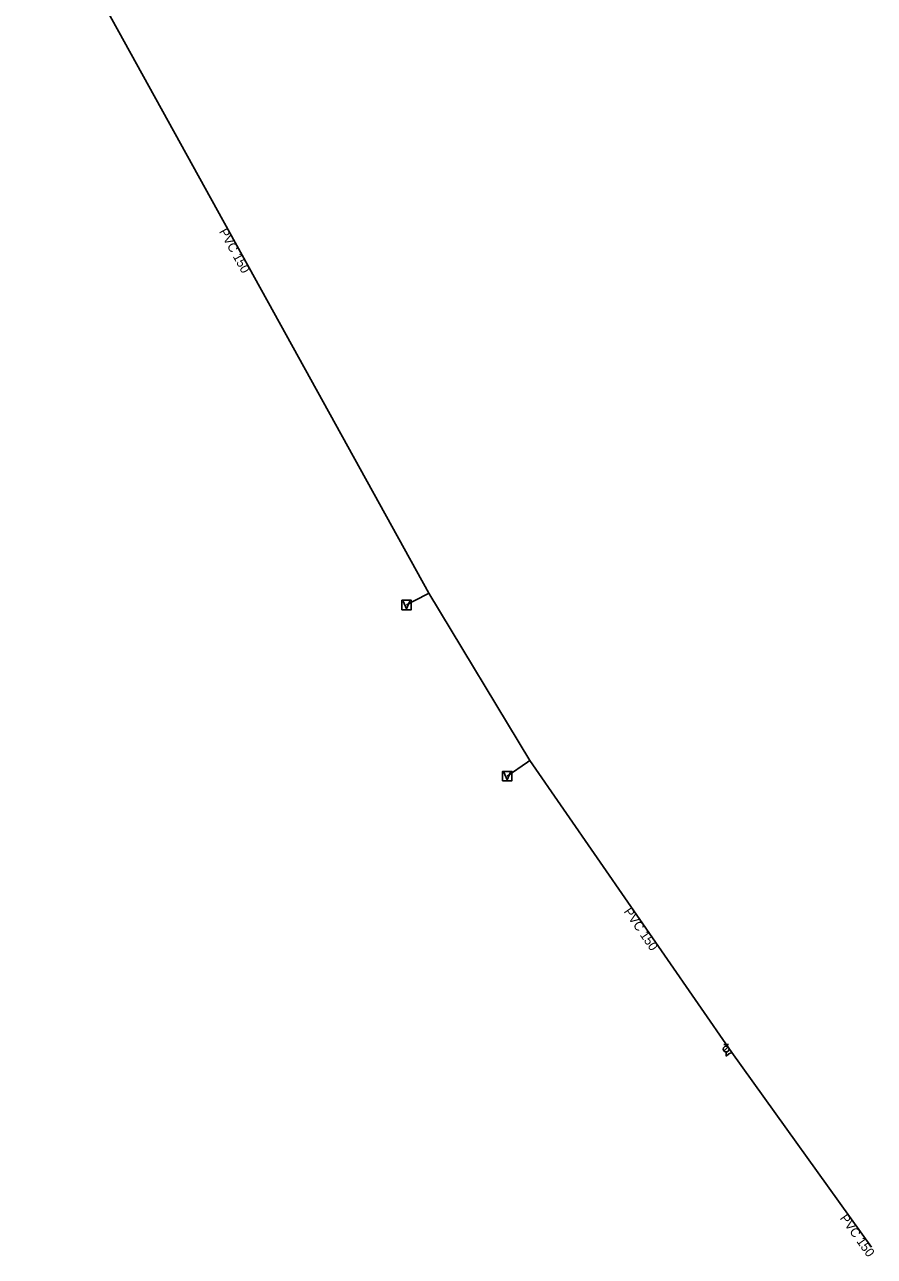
# Model space of a CAD drawing. Extents: x -513141 to -512601, y -1130827 to -1130115.
# Drawn here: x -512802.4 to -512711.5, y -1130827.4 to -1130695.6 of the extents above; entities that cross this region are included whole.
import ezdxf

# ---------------------------------------------------------------- set-up
doc = ezdxf.new("R2010")
doc.units = 0
for name, color, linetype in [('Default', 7, 'Continuous'), ('MoLevel 10', 7, 'Continuous'), ('MoLevel 12', 7, 'Continuous'), ('MoLevel 13', 7, 'Continuous'), ('MoLevel 15', 7, 'Continuous'), ('MoLevel 32', 7, 'Continuous')]:
    doc.layers.add(name, color=color, linetype=linetype)

# ---------------------------------------------------------------- blocks, each defined once
blk = doc.blocks.new('0.05')
at = {"layer": 'Default'}
for p, q in [((-0.01, 0.05), (0.01, 0.05)), ((-0.009, 0.021), (0.009, 0.039)), ((0, 0.0425), (0, 0.05)), ((0, 0), (0, 0.0175))]:
    blk.add_line(p, q, dxfattribs=at)
blk.add_circle((0, 0.03), 0.0125, dxfattribs=at)
blk = doc.blocks.new('0.12')
at = {"layer": 'Default'}
for q in [(-0.035, 0.04), (0.035, 0.04)]:
    blk.add_line((0, -0.04), q, dxfattribs=at)
blk.add_lwpolyline([(-0.05, -0.05), (0.05, -0.05), (0.05, 0.05), (-0.05, 0.05), (-0.05, -0.05)], dxfattribs=at)

msp = doc.modelspace()

# ---------------------------------------------------------------- linework, layer by layer
at = {"layer": 'MoLevel 10'}
for p, q in [((-512759.17, -1130756.39), (-512802.41, -1130678.09)), ((-512748.36, -1130774.31), (-512759.17, -1130756.39)), ((-512726.77, -1130805.53), (-512748.36, -1130774.31)), ((-512727.38, -1130805.93), (-512727.08, -1130805.69)), ((-512727.08, -1130805.69), (-512726.77, -1130805.53)), ((-512711.82, -1130826.39), (-512726.77, -1130805.53))]:
    msp.add_line(p, q, dxfattribs=at)
at = {"layer": 'MoLevel 15'}
for p, q in [((-512761.56, -1130757.67), (-512759.41, -1130756.54)), ((-512759.41, -1130756.54), (-512759.17, -1130756.39)), ((-512750.79, -1130775.97), (-512748.62, -1130774.48)), ((-512748.62, -1130774.48), (-512748.36, -1130774.31))]:
    msp.add_line(p, q, dxfattribs=at)

# ---------------------------------------------------------------- block references
at = {"layer": 'MoLevel 12', "xscale": 25, "yscale": 25}
msp.add_blockref('0.05', (-512727.38, -1130805.93), dxfattribs=at)
at = {"layer": 'MoLevel 13', "xscale": 10, "yscale": 10}
for p in [(-512761.56, -1130757.67), (-512750.79, -1130775.97)]:
    msp.add_blockref('0.12', p, dxfattribs=at)

# ---------------------------------------------------------------- texts
at = {"layer": 'MoLevel 32'}
for rotation, p in [(298.909, (-512781.64, -1130717.71)), (304.6656, (-512738.37, -1130790.47)), (305.6349, (-512715.25, -1130823.28))]:
    msp.add_text('PVC 150', height=0.975, rotation=rotation, dxfattribs=at).set_placement(p)

doc.saveas('drawing.dxf')
